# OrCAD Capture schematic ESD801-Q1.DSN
size A; title: ESD801-Q1 1-Channel ESD Protection Diode; rev: 1.0; note: Datasheet: SLVSI99
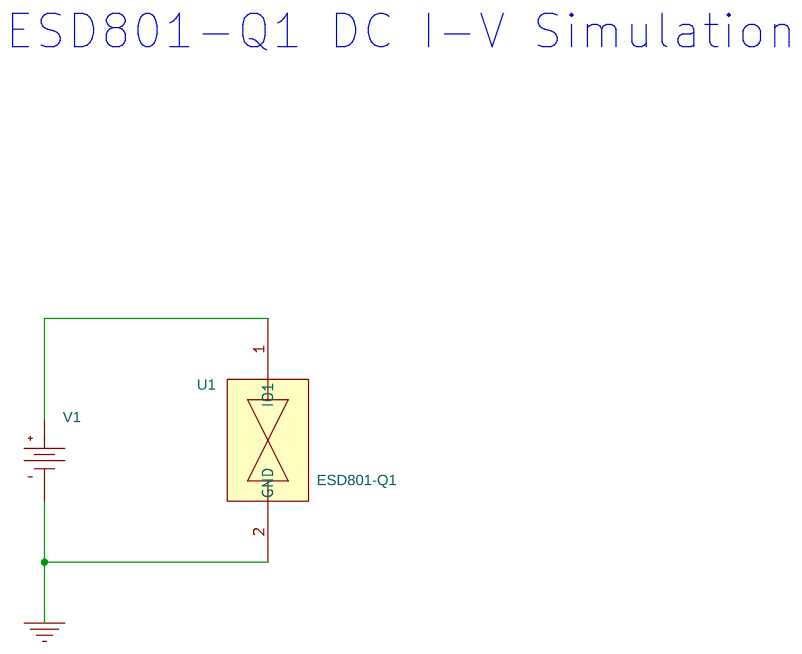
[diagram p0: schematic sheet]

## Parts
U1  ESD801-Q1
V1  VDC

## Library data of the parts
U1 = ESD801-Q1
V1 = VDC

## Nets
0: U1.2(GND) V1.1(-)
N02945: U1.1(IO1) V1.0(+)

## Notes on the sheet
- ESD801-Q1 DC I-V Simulation
